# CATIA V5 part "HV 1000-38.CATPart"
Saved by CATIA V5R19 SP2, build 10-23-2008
Part number: HV 1000-38
Bounding box of the stored display mesh (mm): x -24.865 to 24.865, y -24.997 to 24.997, z 0 to 133
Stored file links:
  C:\Users\Bora\Desktop\3D KATI MODEL- CATIA PART\HV serisi\HV 1000\HV 1000-38.CATPart
  C:\Program Files\Dassault Systemes\B19\intel_a\reffiles\standard\MetricThickPitch.txt
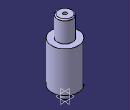
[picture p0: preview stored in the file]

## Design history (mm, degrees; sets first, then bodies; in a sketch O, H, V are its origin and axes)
Body1 (main body)
  Sketch1 on yz-plane, origin (0, 0, 0), H (0, 1, 0), V (0, 0, 1)
    point P1 (14, 131)
    point P3 (14, 131)
    point P8 (8, 17)
    point P10 (8, 1)
    point P11 (8, 17)
    point P12 (8, 1)
    arc A1 centre (12, 131) radius 2 from (14, 131) to (12, 133) ccw
    line L1 (14, 131) -> (14, 94)
    arc A2 centre (8, 18) radius 1 from (8, 19) to (8, 17) ccw
    line L2 (7, 0) -> (8, 1)
    line L3 (8, 17) -> (8, 1)
    line L4 (0, 0) -> (7, 0)
    line L5 (8, 19) -> (25, 19)
    line L6 (14, 94) -> (25, 94)
    line L7 (12, 133) -> (0, 133)
    point P13 (0, 133)
    line L8 (25, 94) -> (25, 19)
    horizontal: L4 H, L6 H
    tangency: L5 A2, L7 A1
    coincidence: P13 V, P1 P3, P8 P11, P10 P12
    vertical: L8 V
  Shaft1: profile Sketch1, axis Sketch1.V, angle 360
  Sketch2 on face of Shaft1 from Sketch1.L4, origin (0, 0, 0), H (1, 0, 0), V (0, -1, 0)
    point P1 (0, 0)
  Hole1: placed by Sketch2, at (0, 0, 0) direction (0, 0, 1), diameter 13.835, depth 19, threaded "M16", thread diameter 16, thread depth 19, pitch 2
  Sketch3 on face of Shaft1 from Sketch1.L7, origin (0, 0, 133), H (1, 0, 0), V (0, 1, 0)
    point P1 (0, 0)
  Hole2: placed by Sketch3, at (0, 0, 133) direction (0, 0, -1), diameter 6.647, depth 15, threaded "M8", thread diameter 8, thread depth 15, pitch 1.25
